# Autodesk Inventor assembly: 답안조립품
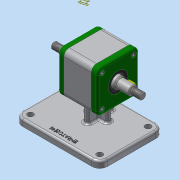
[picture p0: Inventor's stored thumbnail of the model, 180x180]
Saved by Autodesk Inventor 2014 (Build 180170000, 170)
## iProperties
Created: 2020-11
Part Number: 답안조립품
Document SubType Name: Assembly
Designer: kh
Author: kh
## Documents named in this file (9)
- C:\Users\kh\Desktop\701106V1020\답안조립품.iam
- C:\Users\kh\Desktop\701106V1020\본체.ipt
- C:\Users\kh\Desktop\701106V1020\베어링 6004.ipt
- C:\Users\kh\Desktop\701106V1020\축.ipt
- C:\Users\kh\Desktop\701106V1020\커버.ipt
- C:\Users\kh\Desktop\701106V1020\오일 실 17 30 5.ipt
- C:\Users\kh\Desktop\701106V1020\키 5 x 5 x 12.ipt
- C:\Users\kh\Desktop\701106V1020\V-벨트풀리.ipt
- C:\Users\kh\Desktop\701106V1020\볼트 M4.ipt
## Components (2 placed, 1 different names)
1. V-벨트풀리:1
2. V-벨트풀리:2
## Component patterns: 구성요소 패턴 1:2 (2 elements)
